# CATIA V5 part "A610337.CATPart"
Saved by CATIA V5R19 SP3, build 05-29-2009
Part number: D38999/26TF35SN
Revision: -
Definition: A610337
Nomenclature: CONNECTOR, ELEC, PLUG, CIRCULAR, THD, STR, REM CRP CONT
Source: bought
Description: CONNECTOR, ELEC, PLUG, CIRCULAR, THD, STR, REM CRP CONT
Publications: "Logical Termination.1", "Logical Pin.1", "CCP", "CCP_generated(CCP)", "Coincidence_generated(CCP)", "CCP Orientation_generated(CCP)", "BCP", "BCP_generated(BCP)", "Face_generated(BCP)", "BaCP", "BaCP_generated(BaCP)", "BaCP Orientation_generated(BaCP)"
Material "Density=.1010": density 2795.67 kg/m3
Bounding box of the stored display mesh (mm): x -33.16 to 0, y -19.102 to 19.102, z -19.224 to 19.224
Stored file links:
  C:\Users\u305772\OneDrive - Gulfstream Aerospace\AD PAG\Harness\A610337.CATPart
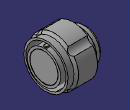
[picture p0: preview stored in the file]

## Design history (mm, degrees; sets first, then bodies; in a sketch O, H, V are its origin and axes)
Parameters
  PartNumber = "D38999/26TF35SN"
  OtherKeywords = "CONNECTORS, ELECTRICAL, PLUG, CIRCULAR, THREADED, STRAIGHT, REMOVABLE CRIMP CONTACTS SERIES III, METRIC"
  Comments = "DD THD: 1.25, VV THD: M28x1.0-6g 0.100R, NICKEL FLUOROCARBON POLYMER OVER A SUITABLE UNDERPLATE (CONDUCTIVE) -65 DEG C TO +175 DEG C, SOCKET"
  CAGECode = "96906"
  WeightComment = "CALCULATED FROM CATIA"
  WeightSource = "Calculated"
  Volume = 2.62058e-05 (volume) {= smartVolume(Body1)}
  Density = 2795.67 (density)
  Weight = 0.161517 {= Volume *Density *2.20462262185}
AxisSystem1: origin (0, 0, 0), X (1, 0, 0), Y (0, 1, 0), Z (0, 0, 1)
Set1
  Point1 "CCP": type Center, Curve edge [face of Shaft1 from Sketch1.L2 | face of Shaft1 from Sketch1.L1]
  Point2 "BaCP": type Center, Curve edge [face of Shaft1 from Sketch1.L17 | face of Shaft1 from Sketch1.L16]
  Point3 "BCP": type Center, Curve edge [face of Shaft1 from Sketch1.L19 | face of Shaft1 from Sketch1.L18]
  Point4: (0, 0, 3.175), relative to Point1, in AxisSystem1
  Point5: (0, 0, 3.175), relative to Point2, in AxisSystem1
  Line1 "Coincidence": type PtPt, FirstPoint Point1, SecondPoint Point3
  Line2 "CCP Orientation": type PtPt, FirstPoint Point1, SecondPoint Point4
  Line3 "BaCP Orientation": type PtPt, FirstPoint Point2, SecondPoint Point5
Body1 (main body)
  Sketch1 on ZX plane of AxisSystem1, origin (0, 0, 0), H (1, 0, 0), V (0, 0, 1)
    point P1 (-0.1, 0)
    line L1 (-0.1, 0) -> (-0.1, 11)
    point P2 (-0.1, 11)
    line L2 (-0.1, 11) -> (-15.01, 11)
    point P3 (-15.01, 11)
    line L3 (-15.01, 11) -> (-15.01, 11.21)
    point P4 (-15.01, 11.21)
    line L4 (-15.01, 11.21) -> (0, 11.21)
    point P5 (0, 11.21)
    line L5 (0, 11.21) -> (0, 13.0825)
    point P6 (0, 13.0825)
    line L6 (0, 13.0825) -> (-15.01, 13.0825)
    point P7 (-15.01, 13.0825)
    line L7 (-15.01, 13.0825) -> (-15.01, 15.875)
    point P8 (-15.01, 15.875)
    line L8 (-15.01, 15.875) -> (-1.54, 15.875)
    point P9 (-1.54, 15.875)
    line L9 (-1.54, 15.875) -> (-1.54, 17.45)
    point P10 (-1.54, 17.45)
    line L10 (-1.54, 17.45) -> (-6.24, 17.45)
    point P11 (-6.24, 17.45)
    line L11 (-6.24, 17.45) -> (-8.04, 19.25)
    point P12 (-8.04, 19.25)
    line L12 (-8.04, 19.25) -> (-23, 19.25)
    point P13 (-23, 19.25)
    line L13 (-23, 19.25) -> (-23, 14)
    point P14 (-23, 14)
    line L14 (-23, 14) -> (-27.745, 14)
    point P15 (-27.745, 14)
    line L15 (-27.745, 14) -> (-28.46, 13.285)
    point P16 (-28.46, 13.285)
    line L16 (-28.46, 13.285) -> (-31, 13.285)
    point P17 (-31, 13.285)
    line L17 (-31, 13.285) -> (-31, 11.39)
    point P18 (-31, 11.39)
    line L18 (-31, 11.39) -> (-33.16, 11.39)
    point P19 (-33.16, 11.39)
    line L19 (-33.16, 11.39) -> (-33.16, 0)
    point P20 (-33.16, 0)
    axis line L20 (-33.16, 0) -> (-0.1, 0)
    point P21 (-0.1, -11)
    point P22 (-0.1, 0)
    construction line L21 (-0.1, 0) -> (-0.1, -11)
    point P23 (-15.01, -11)
    construction line L22 (-0.1, -11) -> (-15.01, -11)
    point P24 (-15.01, -11.21)
    construction line L23 (-15.01, -11) -> (-15.01, -11.21)
    point P25 (0, -11.21)
    construction line L24 (-15.01, -11.21) -> (0, -11.21)
    point P26 (0, -13.0825)
    construction line L25 (0, -11.21) -> (0, -13.0825)
    point P27 (-15.01, -13.0825)
    construction line L26 (0, -13.0825) -> (-15.01, -13.0825)
    point P28 (-15.01, -15.875)
    construction line L27 (-15.01, -13.0825) -> (-15.01, -15.875)
    point P29 (-1.54, -15.875)
    construction line L28 (-15.01, -15.875) -> (-1.54, -15.875)
    point P30 (-1.54, -17.45)
    construction line L29 (-1.54, -15.875) -> (-1.54, -17.45)
    point P31 (-6.24, -17.45)
    construction line L30 (-1.54, -17.45) -> (-6.24, -17.45)
    point P32 (-8.04, -19.25)
    construction line L31 (-6.24, -17.45) -> (-8.04, -19.25)
    point P33 (-23, -19.25)
    construction line L32 (-8.04, -19.25) -> (-23, -19.25)
    point P34 (-23, -14)
    construction line L33 (-23, -19.25) -> (-23, -14)
    point P35 (-27.745, -14)
    construction line L34 (-23, -14) -> (-27.745, -14)
    point P36 (-28.46, -13.285)
    construction line L35 (-27.745, -14) -> (-28.46, -13.285)
    point P37 (-31, -13.285)
    construction line L36 (-28.46, -13.285) -> (-31, -13.285)
    point P38 (-31, -11.39)
    construction line L37 (-31, -13.285) -> (-31, -11.39)
    point P39 (-33.16, -11.39)
    construction line L38 (-31, -11.39) -> (-33.16, -11.39)
    point P40 (-33.16, 0)
    construction line L39 (-33.16, -11.39) -> (-33.16, 0)
    distance L9 P11 = 4.7
    distance L10 L30 = 34.9
    distance L12 L32 = 38.5
    distance L5 L17 = 31
    distance L2 L22 = 22
    angle L16 L15 = 45
    angle L10 L11 = 45
    distance L5 L7 = 15.01
    distance L6 L26 = 26.165
    distance L24 L4 = 22.42
    distance L3 L1 = 14.91
    distance L8 L28 = 31.75
    distance L7 L9 = 13.47
    distance L17 L13 = 8
    distance L17 L19 = 2.16
    distance L38 L18 = 22.78
    distance L36 L16 = 26.57
    distance L34 L14 = 28
    distance L17 P16 = 2.54
    coincidence: P1 H, P5 V, P20 H, L7 L3
    vertical: L1 V, L3 V, L5 V, L7 V, L9 V, L13 V, L17 V, L19 V
    horizontal: L2 H, L4 H, L6 H, L8 H, L10 H, L12 H, L14 H, L16 H, L18 H, L20 H
    symmetry: P2 P21 L20, P1 P22 L20, L1 L21 L20, P3 P23 L20, L2 L22 L20, P4 P24 L20, L3 L23 L20, P5 P25 L20, L4 L24 L20, P6 P26 L20, L5 L25 L20, P7 P27 L20, L6 L26 L20, P8 P28 L20, L7 L27 L20, P9 P29 L20, L8 L28 L20, P10 P30 L20, L9 L29 L20, P11 P31 L20, L10 L30 L20, P12 P32 L20, L11 L31 L20, P13 P33 L20, L12 L32 L20, P14 P34 L20, L13 L33 L20, P15 P35 L20, L14 L34 L20, P16 P36 L20, L15 L35 L20, P17 P37 L20, L16 L36 L20, P18 P38 L20, L17 L37 L20, P19 P39 L20, L18 L38 L20, P20 P40 L20, L19 L39 L20
  Shaft1: profile Sketch1, axis Sketch1.L20, angle 360
  Sketch2 on face of Shaft1 from Sketch1.L5, origin (0, 0, 0), H (0, 1, 0), V (0, 0, 1)
    construction circle A1 centre (0, 0) radius 17.75
    construction line L1 (-17.75, 0) -> (17.75, 0)
    point P1 (-17.75, 0)
    point P2 (17.75, 0)
    arc A2 centre (15.871, 15.871) radius 4.6949 from (11.1803, 15.6704) to (15.6704, 11.1803) ccw
    arc A3 centre (0, 0) radius 19.25 from (15.6704, 11.1803) to (11.1803, 15.6704) ccw
    construction line L2 (0, 0) -> (15.871, 15.871)
    reference projected circle E1 centre (0, 0) radius 19.25 from edge [face of Shaft1 from Sketch1.L12 | face of Shaft1 from Sketch1.L11]
    point P4 (15.6704, 11.1803)
    point P5 (11.1803, 15.6704)
    length L1 = 35.5
    angle L1 L2 = 45
    distance P5 P4 = 6.35
    coincidence: P1 A1, P1 H, P2 A1
    horizontal: L1 H
    tangency: A2 A1, A3 E1
  Pocket1: profile Sketch2, direction (-1, 0, 0), through (limit type 6)
  CircPattern1: of Pocket1, instances 4, angular step 90, axis from face of Shaft1 from Sketch1.L9
  Sketch3 on face of Shaft1 from Sketch1.L5, origin (0, 0, 0), H (0, 1, 0), V (0, 0, 1)
    arc A1 centre (0, 0) radius 13.0825 from (1.27, 13.0207) to (-1.27, 13.0207) ccw
    line L1 (1.27, 14.0326) -> (1.27, 13.0207)
    line L2 (-1.27, 13.0207) -> (-1.27, 14.0326)
    point P1 (1.27, 13.0207)
    point P2 (-1.27, 13.0207)
    reference projected circle E1 centre (0, 0) radius 13.0825 from edge [face of Shaft1 from Sketch1.L6 | face of Shaft1 from Sketch1.L5]
    point P3 (-1.27, -13.0207)
    point P4 (1.27, -13.0207)
    construction arc A2 centre (0, 0) radius 13.0825 from (1.27, -13.0207) to (-1.27, -13.0207) cw
    construction line L3 (-1.27, -13.0207) -> (-1.27, -14.0326)
    construction line L4 (1.27, -14.0326) -> (1.27, -13.0207)
    arc A3 centre (0, 0) radius 14.09 from (1.27, 14.0326) to (-1.27, 14.0326) ccw
    point P6 (1.27, 14.0326)
    point P7 (-1.27, 14.0326)
    point P8 (-1.27, -14.0326)
    point P9 (1.27, -14.0326)
    construction arc A4 centre (0, 0) radius 14.09 from (1.27, -14.0326) to (-1.27, -14.0326) cw
    construction line L5 (0, 14.09) -> (0, -14.09)
    point P11 (0, 14.09)
    point P12 (0, -14.09)
    distance L2 L1 = 2.54
    length L5 = 28.18
    vertical: L1 V, L2 V, L5 V
    symmetry: L1 L2 V, P2 P3 H, P1 P4 H, A1 A2 H, L2 L3 H, L1 L4 H, P7 P8 H, P6 P9 H, A3 A4 H
    tangency: A1 E1
    coincidence: P11 A3, P11 V, P12 A4
  Pad1: profile Sketch3, direction (-1, 0, 0), length 7.24, opposite side length -0.76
